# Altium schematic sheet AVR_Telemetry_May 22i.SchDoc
size 508 x 381 mm; PageSetup: Record=PageOptions¦CenterHorizontal=True¦CenterVertical=True¦PrintScale=1.00¦XCorrection=1.00¦YCorrection=1.00¦PrintKind=1¦BorderSize=5000000¦LeftOffset=0¦BottomOffset=0¦Orientation=2¦PaperLength=1000¦PaperWidth=1000¦Scale=100¦PaperSource=7¦PrintQuality=-3¦MediaType=1¦DitherType=10¦PrintScaleMode=1¦PaperKind=A5¦PaperIndex=11
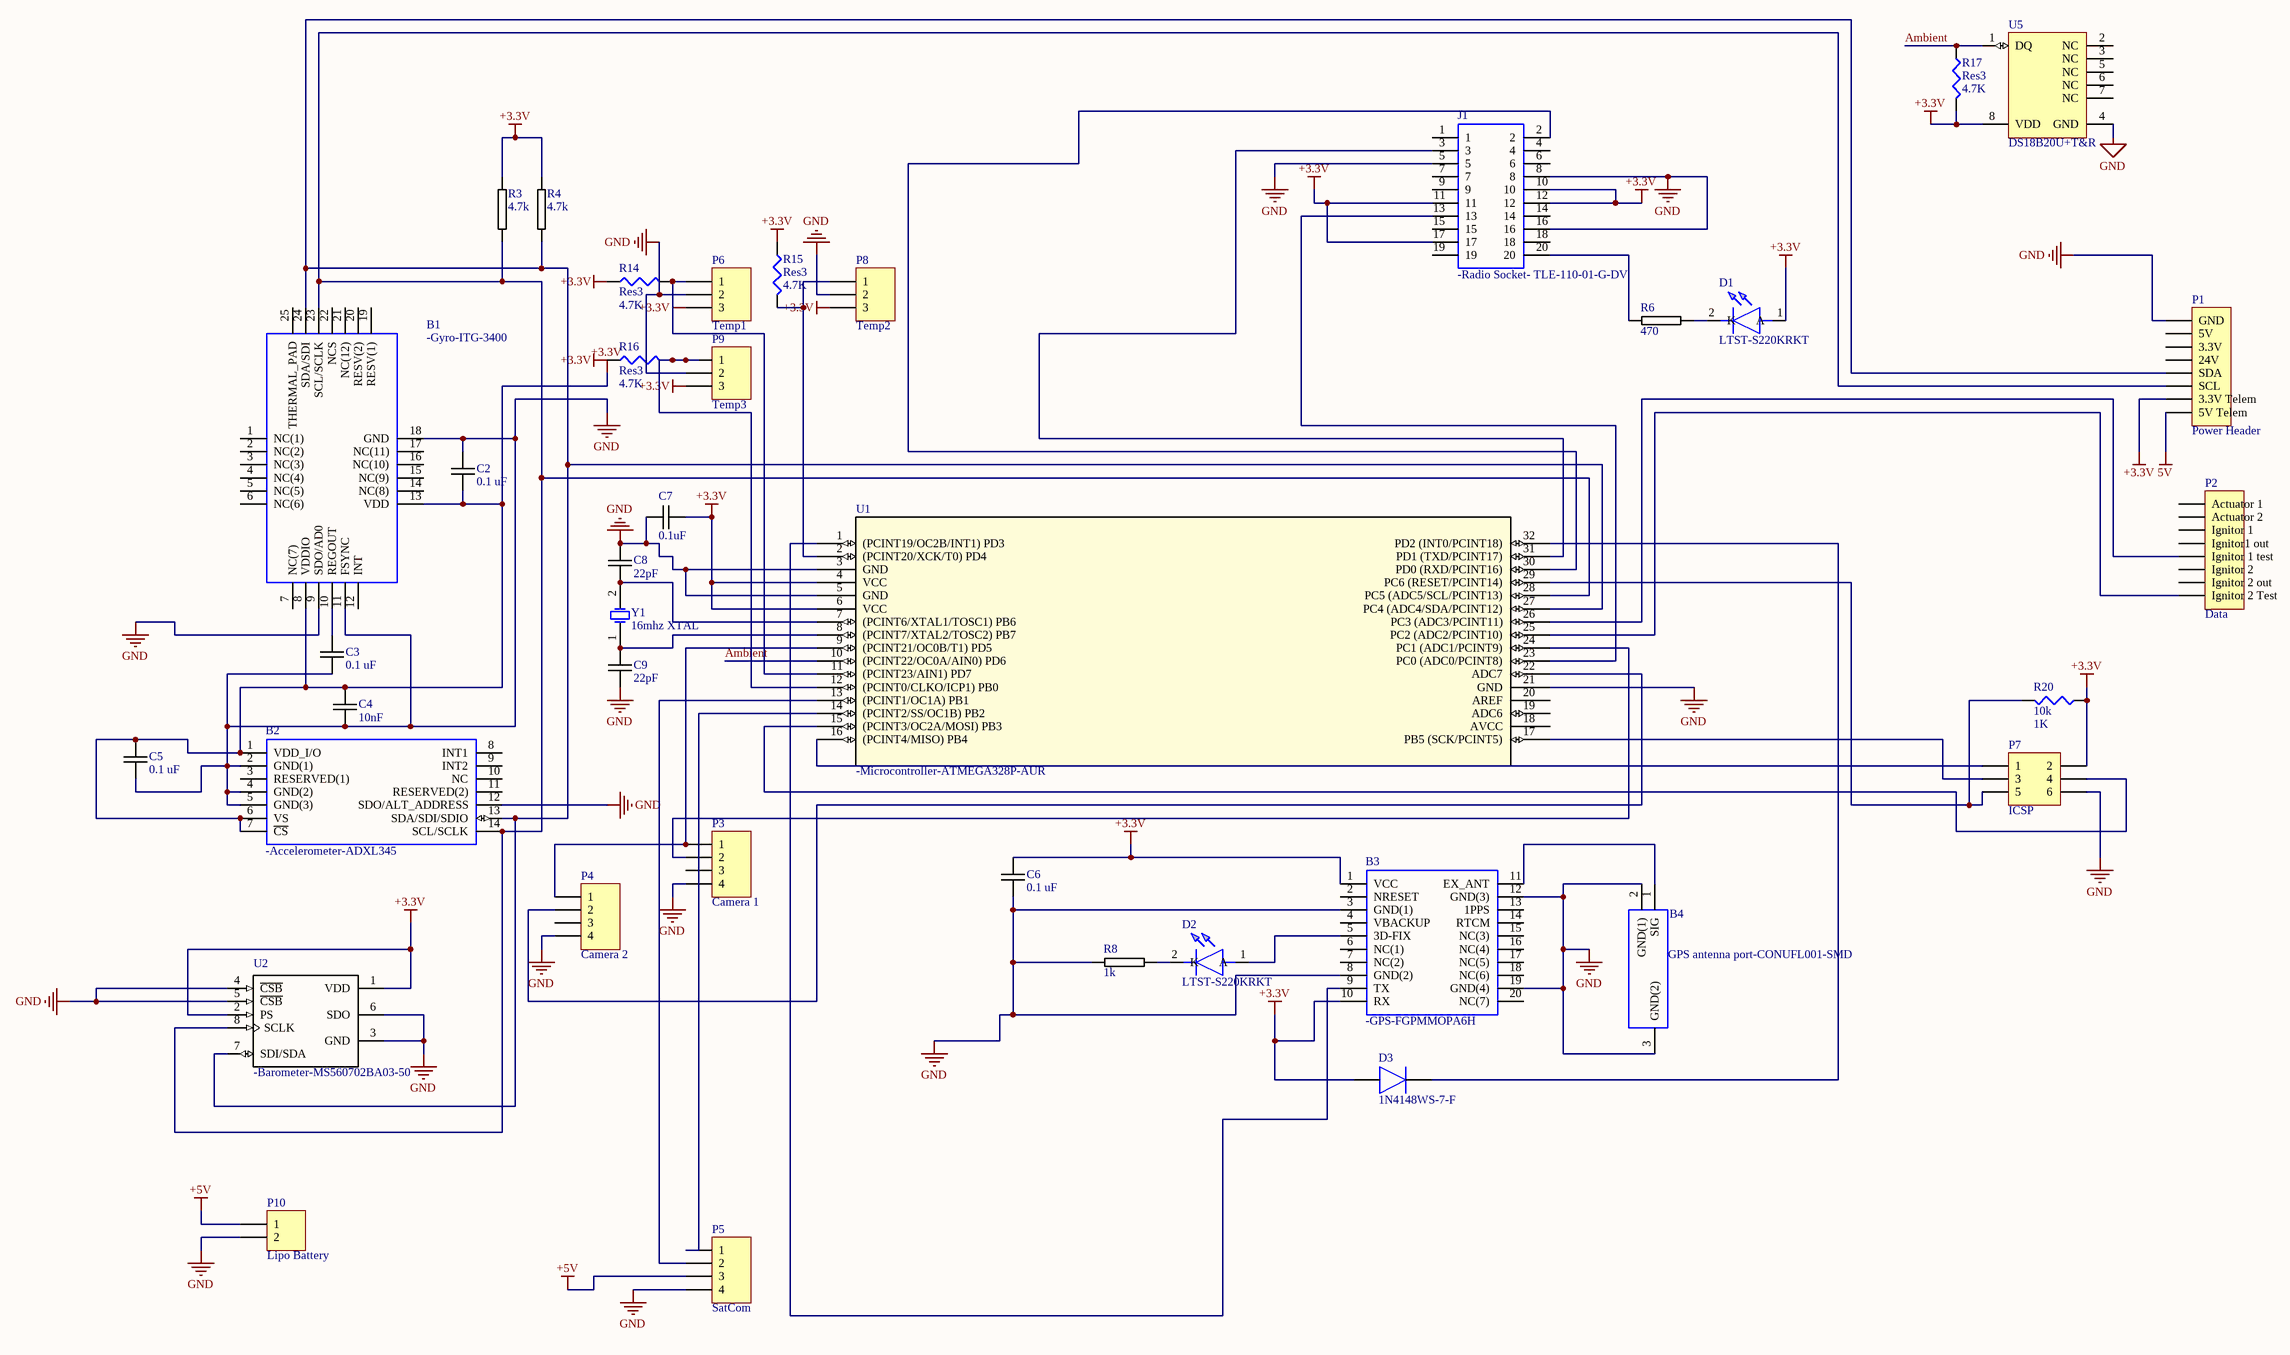
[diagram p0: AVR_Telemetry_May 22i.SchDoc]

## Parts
B1  -Gyro-ITG-3400  [QFN40P300X300X95-25N-D]
B2  -Accelerometer-ADXL345  [LGA_CC-14-1-L]
B3  -GPS-FGPMMOPA6H  [FGPMMOPA6H]
B4  GPS antenna port-CONUFL001-SMD  [CONUFL001-SMD]
C2  0.1 uF  [0603C-GENERIC]
C3  0.1 uF  [0603C-GENERIC]
C4  10nF  [0603C-GENERIC]
C5  0.1 uF  [0603C-GENERIC]
C6  0.1 uF  [0603C-GENERIC]
C7  0.1uF  [0603C-GENERIC]
C8  22pF  [0603C-GENERIC]
C9  22pF  [0603C-GENERIC]
D1  LTST-S220KRKT  [LTST-S220KFKT]
D2  LTST-S220KRKT  [LTST-S220KFKT]
D3  1N4148WS-7-F  [SOD2513X120N]
J1  -Radio Socket- TLE-110-01-G-DV  [TLE-110-01-G-DV]
P1  Power Header  [HDR1X8]
P2  Data  [HDR1X8]
P3  Camera 1  [HDR1X4]
P4  Camera 2  [HDR1X4]
P5  SatCom  [HDR1X4]
P6  Temp1  [HDR1X3]
P7  ICSP  [HDR2X3]
P8  Temp2  [HDR1X3]
P9  Temp3  [HDR1X3]
P10  Lipo Battery  [HDR1X2]
R3  4.7k  [0603R-TBD]
R4  4.7k  [0603R-TBD]
R6  470  [0603R-TBD]
R8  1k  [0603R-TBD]
R14  Res3  value 4.7K  [J1-0603]
R15  Res3  value 4.7K  [J1-0603]
R16  Res3  value 4.7K  [J1-0603]
R17  Res3  value 4.7K  [J1-0603]
R20  10k  value 1K  [J1-0603]
U1  -Microcontroller-ATMEGA328P-AUR  [32A]
U2  -Barometer-MS560702BA03-50  [MS5607-02BA03]
U5  DS18B20U+T&R  [MAXM-U8+1_N]
Y1  16mhz XTAL  [R38]

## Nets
5V: P1.8(5V_Telem)
+3.3V: B1.8(VDDIO) B1.13(VDD) B2.1(VDD_I/O) B2.6(VS) B2.7(~{CS}) B3.1(VCC) B3.10(RX) C2.2 C4.1 C5.1 C6.1 C7.2 D1.1(A) D3.2(A) J1.10 J1.11 J1.12 J1.17 P1.7(3.3V_Telem) P6.3 P7.2 P8.3 P9.3 R3.1 R4.1 R14.1 R15.1 R16.1 R17.2 R20.1 U1.4(VCC) U1.6(VCC) U2.1(VDD) U2.2(PS) U5.8(VDD)
+5V: P5.3 P10.1
GND: B1.9(SDO/AD0) B1.11(FSYNC) B1.18(GND) B2.2(GND(1)) B2.4(GND(2)) B2.5(GND(3)) B2.12(SDO/ALT_ADDRESS) B3.3(GND(1)) B3.8(GND(2)) B3.12(GND(3)) B3.19(GND(4)) B4.2(GND(1)) B4.3(GND(2)) C2.1 C3.2 C4.2 C5.2 C6.2 C7.1 C8.1 C9.2 J1.5 J1.8 J1.16 P1.1(GND) P3.4 P4.4 P5.4 P6.2 P7.6 P8.2 P9.2 P10.2 R8.1 U1.3(GND) U1.5(GND) U1.21(GND) U2.3(GND) U2.4(~{CSB}) U2.5(~{CSB}) U2.6(SDO) U5.4(GND)
Ambient: R17.1 U1.10((PCINT22/OC0A/AIN0)_PD6) U5.1(DQ)
NetB1_10: B1.10(REGOUT) C3.1
NetB1_23: B1.23(SCL/SCLK) B2.14(SCL/SCLK) P1.6(SCL) R3.2 U1.28(PC5_(ADC5/SCL/PCINT13)) U2.8(SCLK)
NetB1_24: B1.24(SDA/SDI) B2.13(SDA/SDI/SDIO) P1.5(SDA) R4.2 U1.27(PC4_(ADC4/SDA/PCINT12)) U2.7(SDI/SDA)
NetB3_5: B3.5(3D-FIX) D2.1(A)
NetB3_9: B3.9(TX) U1.1((PCINT19/OC2B/INT1)_PD3)
NetB3_11: B3.11(EX_ANT) B4.1(SIG)
NetC8_2: C8.2 U1.7((PCINT6/XTAL1/TOSC1)_PB6) Y1.2(OSC2)
NetC9_1: C9.1 U1.8((PCINT7/XTAL2/TOSC2)_PB7) Y1.1(OSC1)
NetD1_2: D1.2(K) R6.2
NetD2_2: D2.2(K) R8.2
NetD3_1: D3.1(K) U1.32(PD2_(INT0/PCINT18))
NetJ1_2: J1.2 U1.30(PD0_(RXD/PCINT16))
NetJ1_3: J1.3 U1.31(PD1_(TXD/PCINT17))
NetJ1_13: J1.13 U1.23(PC0_(ADC0/PCINT8))
NetJ1_20: J1.20 R6.1
NetP2_5: P2.5(Ignitor_1_test) U1.26(PC3_(ADC3/PCINT11))
NetP2_8: P2.8(Ignitor_2_Test) U1.25(PC2_(ADC2/PCINT10))
NetP3_1: P3.1 P4.1 U1.9((PCINT21/OC0B/T1)_PD5)
NetP3_2: P3.2 U1.24(PC1_(ADC1/PCINT9))
NetP4_2: P4.2 U1.22(ADC7)
NetP5_1: P5.1 U1.14((PCINT2/SS/OC1B)_PB2)
NetP5_2: P5.2 U1.13((PCINT1/OC1A)_PB1)
NetP6_1: P6.1 R14.2 U1.11((PCINT23/AIN1)_PD7)
NetP7_1: P7.1 U1.16((PCINT4/MISO)_PB4)
NetP7_3: P7.3 U1.17(PB5_(SCK/PCINT5))
NetP7_4: P7.4 U1.15((PCINT3/OC2A/MOSI)_PB3)
NetP7_5: P7.5 R20.2 U1.29(PC6_(RESET/PCINT14))
NetP8_1: P8.1 R15.2 U1.2((PCINT20/XCK/T0)_PD4)
NetP9_1: P9.1 R16.2 U1.12((PCINT0/CLKO/ICP1)_PB0)

Not connected (* = marked no-connect by the designer): B1 1(NC(1)) 2(NC(2)) 3(NC(3)) 4(NC(4)) 5(NC(5)) 6(NC(6)) 7(NC(7)) 12(INT) 14(NC(8)) 15(NC(9)) 16(NC(10)) 17(NC(11)) 19(RESV(1)) 20(RESV(2)) 21(NC(12)) 22(NCS) 25(THERMAL_PAD); B2 3(RESERVED(1)) 8(INT1) 9(INT2) 10(NC) 11(RESERVED(2)); B3 2(NRESET) 4(VBACKUP) 6(NC(1)) 7(NC(2)) 13(1PPS) 14(RTCM) 15(NC(3)) 16(NC(4)) 17(NC(5)) 18(NC(6)) 20(NC(7)); J1 1 4 6 7 9 14 15 18 19; P1 2(5V) 3(3.3V) 4(24V); P2 1(Actuator_1) 2(Actuator_2) 3(Ignitor_1) 4(Ignitor1_out) 6(Ignitor_2) 7(Ignitor_2_out); P3 3; P4 3; U1 18(AVCC) 19(ADC6) 20(AREF); U5 2(NC) 3(NC) 5(NC) 6(NC) 7(NC)

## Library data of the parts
B1 = ITG-3400: 3-axis gyroscope, I2C at 400kHz or SPI at 1MHz, QFN-24; Manufacturer_Name: INVENSENSE; Geometry.Height: 0.95mm
B2 = ADXL345: 3-Axis Accelerometer IC; Manufacturer_Name: Analog Devices
B3 = FGPMMOPA6H: GPS Standalone Module, 20-pin; Manufacturer_Name: GlobalTop Technology Inc.
B4 = CONUFL001-SMD: RF Connectors / Coaxial Connectors U.FL Straight Surface Mount Jack; Manufacturer_Name: Linx Technologies
C2-C9 = 0603C-1NF-50V-X7R: CAPACITOR 0603 CERAMIC
D1 D2 = LTST-S220KRKT: Lite-On LTST-S220KRKT Red LED, 631 nm, 2012 (0805) Side View, Rectangle Lens SMD Package
D3 = 1N4148WS-7-F: Diode Switching 150mA 75V 200mW SOD323 Diodes Inc 1N4148WS-7-F Switching Diode, 150mA 75V, 2-Pin SOD-323; Manufacturer_Name: Diodes Inc.; Allied_Number: 71028126; Geometry.Height: 1.2mm
J1 = TLE-110-01-G-DV: Receptacle 2mm SMT 10+10way Samtec TLE Series 2mm Pitch 20 Way 2 Row Straight PCB Socket, Surface Mount, Solder Termination
P1 P2 = Header 8: Header, 8-Pin
P3-P5 = Header 4: Header, 4-Pin
P6 P8 P9 = Header 3: Header, 3-Pin
P7 = Header 3X2: Header, 3-Pin, Dual row
P10 = Header 2: Header, 2-Pin
R3 R4 R6 R8 = 0603R-TBD: RESISTOR 0603 VALUE TO BE DETERMINED
R14-R17 R20 = Res3: Resistor
U1 = ATMEGA328P-AUR: Imported; Vendor: Atmel; Built_By: EMA_UL_Team; C: Copyright (C) 2015 Accelerated Designs. All rights reserved
U2 = MS560702BA03-50: MS5607-02BA03 Series 3 V 1 to 120 kPa Absolute Barometric Pressure Sensor; MF: TE Connectivity
U5 = DS18B20U+T&R: High-Precision 1-Wire Digital Thermometer, -55 to 125 degC, 8-Pin SOP (U8+1), Pb-Free, Tape and Reel; Multi Droppable: Yes; Sensor Type: Local; Temp. Thresh.: Programmable (NV)
Y1 = XTAL: Crystal Oscillator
